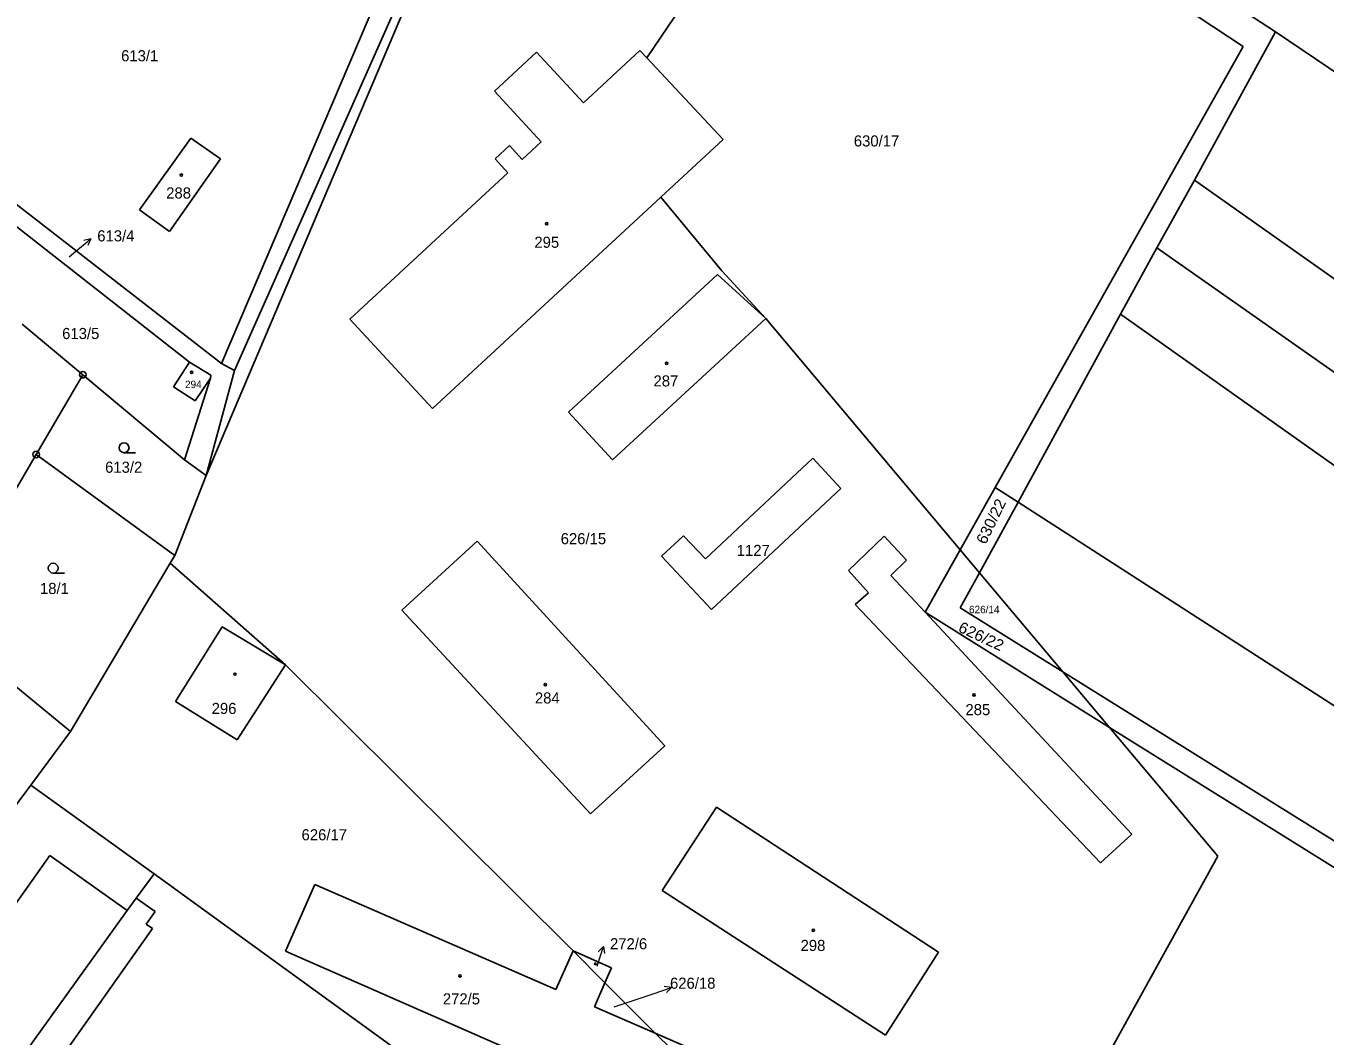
# Model space of a CAD drawing. Extents: x -694609 to -690140, y -1033292 to -1029794.
# Drawn here: x -692303.2 to -692104.2, y -1031705.3 to -1031550.7 of the extents above; entities that cross this region are included whole.
import ezdxf
from ezdxf.enums import TextEntityAlignment as Align

# ---------------------------------------------------------------- set-up
doc = ezdxf.new("R2010")
doc.units = 0
doc.header["$LTSCALE"] = 0.68
for name, color, linetype, lineweight in [('1', 7, 'Continuous', 25), ('3', 7, 'Continuous', 25), ('5', 7, 'Continuous', 25), ('7', 7, 'Continuous', 13), ('8', 7, 'Continuous', 25)]:
    doc.layers.add(name, color=color, linetype=linetype, lineweight=lineweight)
doc.layers.add('2', color=7, linetype='Continuous')

msp = doc.modelspace()

# ---------------------------------------------------------------- linework, layer by layer
at = {"layer": '1'}
for p, q in [((-692205.16, -1031490.59), (-692111.95, -1031551.64)), ((-692209.35, -1031492.82), (-692116.89, -1031553.87)), ((-692234.23, -1031519.96), (-692271.28, -1031603.49)), ((-692208.18, -1031555.62), (-692186.22, -1031523.03)), ((-692237.48, -1031529.76), (-692275.6, -1031619.54)), ((-692273.27, -1031602.4), (-692244.77, -1031535.57)), ((-692111.95, -1031551.64), (-692124.36, -1031574.32)), ((-692111.95, -1031551.64), (-691959.58, -1031654.88)), ((-692225.05, -1031554.75), (-692231.49, -1031560.72)), ((-692217.88, -1031562.5), (-692225.05, -1031554.75)), ((-692217.88, -1031562.5), (-692209.23, -1031554.5)), ((-692209.23, -1031554.5), (-692208.18, -1031555.62)), ((-692116.89, -1031553.87), (-692154.85, -1031621.39)), ((-692208.18, -1031555.62), (-692196.48, -1031568.1)), ((-692273.27, -1031602.4), (-692330.34, -1031558.16)), ((-692231.49, -1031560.72), (-692224.33, -1031568.46)), ((-692277.96, -1031567.9), (-692285.83, -1031578.87)), ((-692277.96, -1031567.9), (-692273.43, -1031571.08)), ((-692227.23, -1031571.15), (-692224.33, -1031568.46)), ((-692196.48, -1031568.1), (-692206.02, -1031576.93)), ((-692229.18, -1031569.05), (-692231.38, -1031571.08)), ((-692227.23, -1031571.15), (-692229.18, -1031569.05)), ((-692281.23, -1031582.17), (-692273.43, -1031571.08)), ((-692231.38, -1031571.08), (-692229.43, -1031573.19)), ((-692253.65, -1031595.62), (-692229.43, -1031573.19)), ((-692124.36, -1031574.32), (-692130.13, -1031584.7)), ((-692124.36, -1031574.32), (-691983.86, -1031673.64)), ((-692278.15, -1031602.2), (-692311.08, -1031576.44)), ((-692206.02, -1031576.93), (-692240.99, -1031609.31)), ((-692196.7, -1031588.22), (-692206.02, -1031576.93)), ((-692281.23, -1031582.17), (-692285.83, -1031578.87)), ((-692130.13, -1031584.7), (-692135.67, -1031594.86)), ((-692130.13, -1031584.7), (-691993.09, -1031680.81)), ((-692196.7, -1031588.22), (-692189.98, -1031595.49)), ((-692197.37, -1031588.76), (-692220.17, -1031609.83)), ((-692189.98, -1031595.49), (-692197.37, -1031588.76)), ((-692303.76, -1031596.37), (-692294.5, -1031604.11)), ((-692240.99, -1031609.31), (-692253.65, -1031595.62)), ((-692189.98, -1031595.49), (-692213.44, -1031617.12)), ((-692189.98, -1031595.49), (-692160.2, -1031630.91)), ((-692135.67, -1031594.86), (-692151.35, -1031623.64)), ((-692135.67, -1031594.86), (-692002.96, -1031688.9)), ((-692280.62, -1031605.99), (-692278.15, -1031602.2)), ((-692278.15, -1031602.2), (-692274.9, -1031604.2)), ((-692271.28, -1031603.49), (-692273.27, -1031602.4)), ((-692301.64, -1031616.32), (-692294.5, -1031604.11)), ((-692278.93, -1031617.16), (-692294.5, -1031604.11)), ((-692275.6, -1031619.54), (-692271.28, -1031603.49)), ((-692274.9, -1031604.2), (-692274.94, -1031604.62)), ((-692280.62, -1031605.99), (-692277.32, -1031608.11)), ((-692274.94, -1031604.62), (-692278.93, -1031617.16)), ((-692274.94, -1031604.62), (-692277.32, -1031608.11)), ((-692213.44, -1031617.12), (-692220.17, -1031609.83)), ((-692316.68, -1031642.01), (-692301.64, -1031616.32)), ((-692280.43, -1031631.77), (-692301.64, -1031616.32)), ((-692275.6, -1031619.54), (-692278.93, -1031617.16)), ((-692182.79, -1031616.91), (-692199.22, -1031632.32)), ((-692178.48, -1031621.51), (-692182.79, -1031616.91)), ((-692280.43, -1031631.77), (-692275.6, -1031619.54)), ((-692198.26, -1031640.06), (-692178.48, -1031621.51)), ((-692154.85, -1031621.39), (-692160.2, -1031630.91)), ((-692154.85, -1031621.39), (-692151.35, -1031623.64)), ((-692151.35, -1031623.64), (-692157.25, -1031634.42)), ((-692151.35, -1031623.64), (-692023.78, -1031705.82)), ((-692245.67, -1031640.15), (-692234.15, -1031629.6)), ((-692202.56, -1031628.76), (-692205.91, -1031631.9)), ((-692199.22, -1031632.32), (-692202.56, -1031628.76)), ((-692171.87, -1031628.81), (-692177.31, -1031634.08)), ((-692171.87, -1031628.81), (-692168.45, -1031632.52)), ((-692281.12, -1031632.96), (-692280.43, -1031631.77)), ((-692205.91, -1031631.9), (-692198.26, -1031640.06)), ((-692160.2, -1031630.91), (-692165.57, -1031640.46)), ((-692160.2, -1031630.91), (-692157.25, -1031634.42)), ((-692296.39, -1031658.75), (-692281.12, -1031632.96)), ((-692281.12, -1031632.96), (-692263.47, -1031648.52)), ((-692174.26, -1031637.53), (-692177.31, -1031634.08)), ((-692168.45, -1031632.52), (-692170.81, -1031634.83)), ((-692157.25, -1031634.42), (-692160.2, -1031639.81)), ((-692157.25, -1031634.42), (-692144.49, -1031649.61)), ((-692170.81, -1031634.83), (-692165.57, -1031640.46)), ((-692176.27, -1031639.29), (-692174.26, -1031637.53)), ((-692216.8, -1031671.34), (-692245.67, -1031640.15)), ((-692176.27, -1031639.29), (-692138.74, -1031678.84)), ((-692160.2, -1031639.81), (-692144.49, -1031649.61)), ((-692316.68, -1031642.01), (-692296.39, -1031658.75)), ((-692165.57, -1031640.46), (-692137.35, -1031658.1)), ((-692165.57, -1031640.46), (-692133.95, -1031674.43)), ((-692273.16, -1031642.72), (-692280.29, -1031654.13)), ((-692263.47, -1031648.52), (-692273.16, -1031642.72)), ((-692263.47, -1031648.52), (-692270.86, -1031660)), ((-692219.47, -1031692.33), (-692263.47, -1031648.52)), ((-692144.49, -1031649.61), (-692035.82, -1031717.37)), ((-692144.49, -1031649.61), (-692137.35, -1031658.1)), ((-692280.29, -1031654.13), (-692270.86, -1031660)), ((-692137.35, -1031658.1), (-692038.82, -1031719.67)), ((-692137.35, -1031658.1), (-692120.78, -1031677.81)), ((-692296.39, -1031658.75), (-692302.47, -1031666.94)), ((-692302.47, -1031666.94), (-692321.31, -1031692.32)), ((-692283.59, -1031680.54), (-692302.47, -1031666.94)), ((-692205.81, -1031683.05), (-692197.51, -1031670.34)), ((-692197.51, -1031670.34), (-692163.54, -1031692.52)), ((-692133.95, -1031674.43), (-692138.74, -1031678.84)), ((-692334.77, -1031727.41), (-692299.54, -1031677.74)), ((-692299.54, -1031677.74), (-692287.71, -1031686.16)), ((-692120.78, -1031677.81), (-692145.66, -1031722.81)), ((-692283.59, -1031680.54), (-692286.34, -1031684.26)), ((-692245.5, -1031708.12), (-692283.59, -1031680.54)), ((-692263.5, -1031692.38), (-692259, -1031682.14)), ((-692259, -1031682.14), (-692222.11, -1031698.23)), ((-692171.67, -1031705.24), (-692205.81, -1031683.05)), ((-692287.71, -1031686.16), (-692323.37, -1031735.66)), ((-692286.34, -1031684.26), (-692287.71, -1031686.16)), ((-692286.34, -1031684.26), (-692283.44, -1031686.29)), ((-692284.8, -1031688.23), (-692283.44, -1031686.29)), ((-692283.83, -1031688.91), (-692297.6, -1031708.4)), ((-692283.83, -1031688.91), (-692284.8, -1031688.23)), ((-692210.65, -1031715.54), (-692263.5, -1031692.38)), ((-692222.11, -1031698.23), (-692219.47, -1031692.33)), ((-692219.47, -1031692.33), (-692214.59, -1031697.21)), ((-692219.47, -1031692.33), (-692213.58, -1031694.9)), ((-692163.54, -1031692.52), (-692171.67, -1031705.24)), ((-692213.58, -1031694.9), (-692214.59, -1031697.21)), ((-692214.59, -1031697.21), (-692216.18, -1031700.86)), ((-692214.59, -1031697.21), (-692206.91, -1031704.9)), ((-692216.18, -1031700.86), (-692206.91, -1031704.9)), ((-692204.33, -1031707.41), (-692206.91, -1031704.9))]:
    msp.add_line(p, q, dxfattribs=at)
for points in [[(-692234.15, -1031629.6), (-692205.44, -1031660.93), (-692216.8, -1031671.34)], [(-692206.91, -1031704.9), (-692187.92, -1031713.17), (-692192.5, -1031723.49)]]:
    msp.add_lwpolyline(points, dxfattribs=at)
at = {"layer": '3'}
for p, q in [((-692288.173, -1031616.05), (-692286.423, -1031616.05)), ((-692299.033, -1031634.48), (-692297.283, -1031634.48))]:
    msp.add_line(p, q, dxfattribs=at)
for centre in [(-692288.1729, -1031615.2998), (-692299.0329, -1031633.7298)]:
    msp.add_circle(centre, 0.75, dxfattribs=at)
at = {"layer": '5'}
for centre, radius in [((-692279.4168, -1031573.5592), 0.175), ((-692223.4968, -1031581.0092), 0.175), ((-692205.1568, -1031602.3792), 0.175), ((-692277.8468, -1031603.7492), 0.175), ((-692271.2168, -1031649.9592), 0.175), ((-692223.6968, -1031651.5592), 0.175), ((-692158.0868, -1031653.1292), 0.175), ((-692182.7068, -1031689.1692), 0.175), ((-692236.7668, -1031696.1492), 0.175), ((-692216.0546, -1031694.2994), 0.1172)]:
    msp.add_circle(centre, radius, dxfattribs=at)
at = {"layer": '7'}
for p, q in [((-692293.271, -1031583.291), (-692294.36, -1031583.551)), ((-692214.833, -1031691.64), (-692215.604, -1031692.451)), ((-692204.393, -1031697.913), (-692205.502, -1031697.766))]:
    msp.add_line(p, q, dxfattribs=at)
for points in [[(-692296.58, -1031586.07), (-692295.57, -1031585.22), (-692293.271, -1031583.291), (-692293.716, -1031584.318)], [(-692215.76, -1031694.67), (-692215.71, -1031694.51), (-692214.833, -1031691.64), (-692214.647, -1031692.744)], [(-692213.18, -1031700.88), (-692207.23, -1031698.89), (-692204.393, -1031697.913), (-692205.176, -1031698.712)]]:
    msp.add_lwpolyline(points, dxfattribs=at)
at = {"layer": '8'}
for centre, radius in [((-692294.5, -1031604.1099), 0.5), ((-692294.5, -1031604.1099), 0.0303), ((-692301.64, -1031616.3199), 0.5), ((-692301.64, -1031616.3199), 0.0303)]:
    msp.add_circle(centre, radius, dxfattribs=at)

# ---------------------------------------------------------------- texts
at = {"layer": '2'}
for s, height, p in [('613/1', 1.7, (-692285.79, -1031556.135)), ('630/17', 1.7, (-692173.02, -1031569.175)), ('288', 1.7, (-692279.839, -1031577.145)), ('295', 1.7, (-692223.489, -1031584.685)), ('613/5', 1.7, (-692294.81, -1031598.655)), ('287', 1.7, (-692205.259, -1031605.915)), ('294', 1.14, (-692277.58, -1031606.165)), ('613/2', 1.7, (-692288.24, -1031619.125)), ('626/15', 1.7, (-692217.88, -1031630.065)), ('1127', 1.7, (-692191.89, -1031631.865)), ('18/1', 1.7, (-692298.839, -1031637.685)), ('626/14', 1.14, (-692156.539, -1031640.625)), ('296', 1.7, (-692272.879, -1031656.055)), ('284', 1.7, (-692223.409, -1031654.445)), ('285', 1.7, (-692157.519, -1031656.235)), ('626/17', 1.7, (-692257.54, -1031675.395)), ('298', 1.7, (-692182.749, -1031692.335)), ('626/18', 1.7, (-692201.15, -1031698.115)), ('272/5', 1.7, (-692236.55, -1031700.515))]:
    msp.add_text(s, height=height, dxfattribs=at).set_placement(p, align=Align.CENTER)
for s, p in [('613/4', (-692292.28, -1031583.705)), ('272/6', (-692213.81, -1031692.075))]:
    msp.add_text(s, height=1.7, dxfattribs=at).set_placement(p)
at = {"layer": '2', "width": 1.05}
for s, rotation, p in [('630/22', 64, (-692154.7349, -1031626.9356)), ('626/22', 335, (-692157.3467, -1031644.9301))]:
    msp.add_text(s, height=1.7, rotation=rotation, dxfattribs=at).set_placement(p, align=Align.CENTER)

doc.saveas('drawing.dxf')
